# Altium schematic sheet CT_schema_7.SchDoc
size 287 x 160 mm
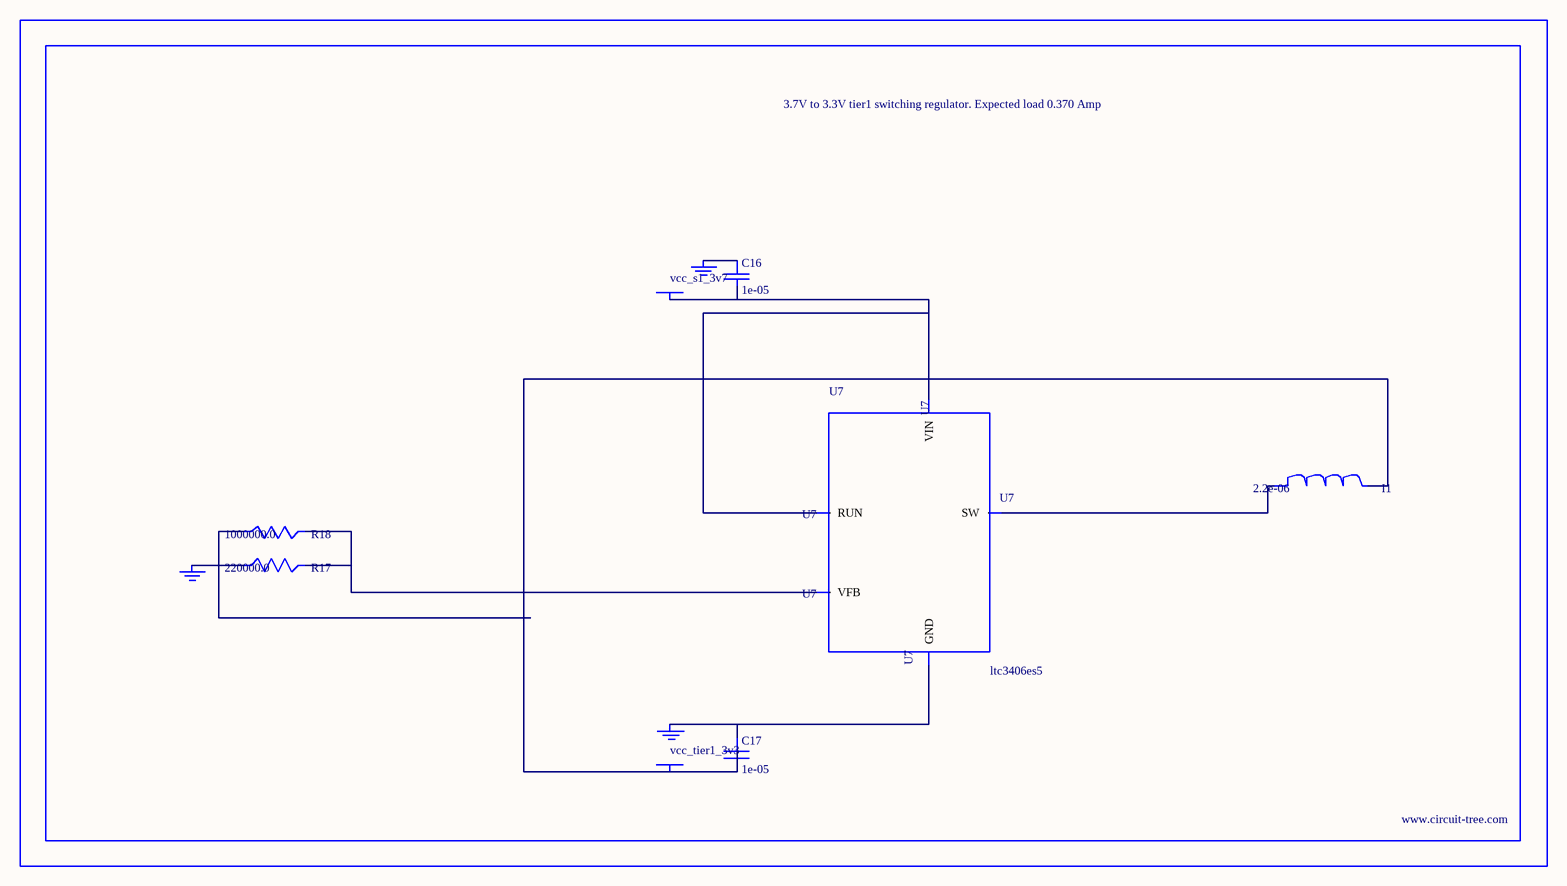
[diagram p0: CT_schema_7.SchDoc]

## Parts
BORDER6  (no value)
C16  1e-05  [C0805]
C17  1e-05  [C0805]
GND_INSTANCE_6_0  (no value)
GND_INSTANCE_6_1  (no value)
GND_INSTANCE_6_2  (no value)
I1  2.2e-06  [L0805]
POWER_INSTANCE_6_0  vcc_tier1_3v3
POWER_INSTANCE_6_1  vcc_s1_3v7
R17  220000.0  [R0603]
R18  1000000.0  [R0603]
U7  ltc3406es5  [TSOT-23-5]

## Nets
NetC16_1: C16.1 GND_INSTANCE_6_1.0(GND)
NetC16_2: C16.2 POWER_INSTANCE_6_1.0(PWR) U7.1(RUN) U7.4(VIN)
NetC17_1: C17.1 GND_INSTANCE_6_0.0(GND) U7.2(GND)
NetC17_2: C17.2 I1.2 POWER_INSTANCE_6_0.0(PWR) R18.1
NetGND_INSTANCE_6_2_0: GND_INSTANCE_6_2.0(GND) R17.1
NetI1_1: I1.1 U7.3(SW)
NetR17_2: R17.2 R18.2 U7.5(VFB)

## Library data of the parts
BORDER6 = BORDER_PAGE6
C16 C17 = C0805C106K8RACTU
GND_INSTANCE_6_0-GND_INSTANCE_6_2 = GND
I1 = L0805C2R2MDWIT
POWER_INSTANCE_6_0 POWER_INSTANCE_6_1 = PWR
R17 = RC0603JR-07220KL
R18 = RC0603JR-071ML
